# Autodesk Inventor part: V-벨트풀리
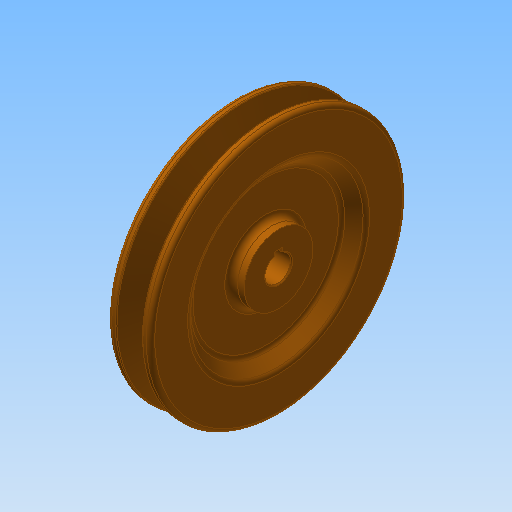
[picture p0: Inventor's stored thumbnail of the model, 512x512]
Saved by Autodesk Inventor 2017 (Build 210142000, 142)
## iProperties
Created: 2015-12
Part Number: V-벨트풀리
Document SubType Name: Modeling
Designer: mdu
Density: 8.08 g/cm^3
Material: 스테인리스강
Appearance: 주황색
Mass: 1135.6 g
Surface Area: 369.424 cm^2
Volume: 140.544 cm^3
Author: mdu
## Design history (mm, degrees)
sketch "스케치1"
  geometry: L1 (-10, 0)-(10, 0); L2 (-10, 0)-(-10, 16); L3 (-10, 16)-(-4, 16); L4 (-4, 16)-(-4, 35); L5 (-4, 35)-(-10, 41); L6 (-10, 41)-(-10, 59.5); L7 (-10, 59.5)-(-6.062, 59.5); L8 (-6.062, 59.5)-(-2.001, 47); L9 (-2.001, 47)-(2.001, 47); L10 (2.001, 47)-(6.062, 59.5); L11 (6.062, 59.5)-(10, 59.5); L12 (10, 59.5)-(10, 41); L13 (10, 41)-(4, 35); L14 (4, 35)-(4, 16); L15 (4, 16)-(10, 16); L16 (10, 16)-(10, 0); L17 (-4.6, 55)-(4.6, 55); 2 further points
  constraints: 34 end point, 7 parallel, 6 equal length, 5 collinear, 3 perpendicular, 2 point on line, 1 coincident, 1 horizontal, 1 midpoint
  dimensions: "d0" = 20 distance of L1.start L1.end; "d1" = 9.2 distance of L17.start L17.end; "d2" = 36 deg angle of L10 L8; "d3" = 4.5 distance between parallel lines of L7 L17; "d4" = 8 distance between parallel lines of L9 L17; "d6" = 110 diameter of L17 L1; "d7" = 32 diameter of L3 L1; "d8" = 82 diameter of L5.end L1; "d9" = 6 distance of L2.end L3.end; "d10" = 135 deg angle of L4 L5
revolve "회전1" sketch "스케치1" stored, may be unused: angle "d11" = 90 deg
fillet "모깎기1" dims "d12" = 2, "d13" = 0.5, "d14" = 1, "d15" = 3
sketch "스케치2"
  geometry: L1 (-2, 5.657)-(-2, 7.8); L2 (-2, 7.8)-(2, 7.8); L3 (2, 7.8)-(2, 5.657); A1 r 6 centre (0, 0) between (-2, 5.657) and (2, 5.657); 1 further point
  constraints: 6 end point, 2 parallel, 2 point on circle, 1 centre point, 1 coincident, 1 perpendicular, 1 vertical
  dimensions: "d16" = 12 diameter of A1; "d17" = 4 distance of L1.end L2.end; "d18" = 13.8 dimension on A1 L2 (computed from d16)
extrude "돌출1" cut sketch "스케치2" stored distance "d19" = 10; taper "d20" = 0 deg
chamfer "모따기2" distance "d24" = 0.5; stored, may be unused: second distance "d25" = 2, angle "d26" = 45 deg
sketch "스케치3" dims "d27" = 100
  geometry: C1 r 2.5 at (0, 50); 2 further points
  constraints: 2 vertical alignment, 1 centre point, 1 coincident, 2 other
  dimensions: "d28" = 5 diameter of C1
extrude "돌출2" join sketch "스케치3" distance "d29" = 1; taper "d30" = 0 deg
node "솔리드1"
